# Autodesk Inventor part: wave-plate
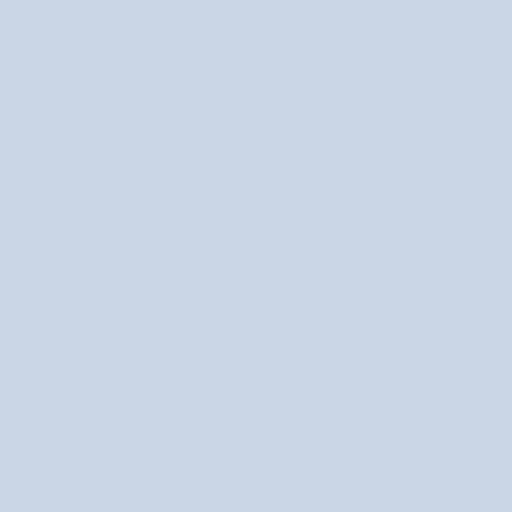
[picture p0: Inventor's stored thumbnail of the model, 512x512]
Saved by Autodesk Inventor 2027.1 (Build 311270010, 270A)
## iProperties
Created: 2026-08
Part Number: wave-plate
Material: Generic
Document SubType Name: Modeling
Designer: dunge
Density: 1 g/cm^3
Appearance: Default
Author: dunge
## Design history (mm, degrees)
sketch "Sketch1"
  geometry: C1 r 12.7 at (0, 0); 1 further point
  constraints: 1 centre point, 1 coincident
  dimensions: "d0" = 25.4 diameter of C1
extrude "Extrusion1" new body sketch "Sketch1" stored distance "d1" = 0.635; taper "d2" = 0 deg
body "Solid1"
node "Finishes"
node "Finish1" dims "Finish1_Area" = 106.40857
